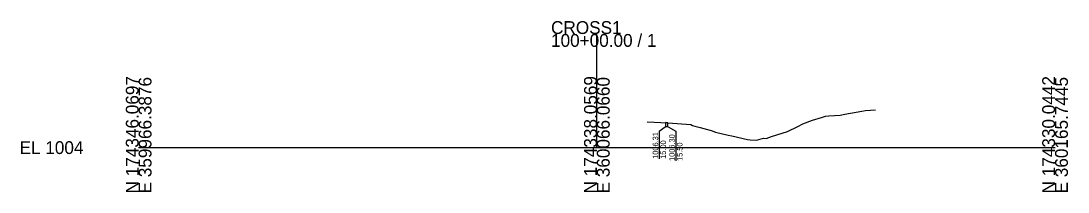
# Model space of a CAD drawing. Extents: x -26 to 1403, y -10 to 11027.
# Drawn here: x 1174.3 to 1402.8, y 3490.3 to 3527.6 of the extents above; entities that cross this region are included whole.
import ezdxf

# ---------------------------------------------------------------- set-up
doc = ezdxf.new("R2010")
doc.units = 0
for name, color, linetype in [('Default', 7, 'Continuous'), ('P_E_XS_Ground', 7, 'Continuous'), ('P_XS_EAR_CommonGrnd', 7, 'Continuous'), ('P_XS_Lane', 7, 'Continuous'), ('P_XS_Rock', 7, 'Continuous')]:
    doc.layers.add(name, color=color, linetype=linetype)

msp = doc.modelspace()

# ---------------------------------------------------------------- linework, layer by layer
at = {"layer": 'Default'}
for p, q in [((1300, 3500), (1300, 3524.78)), ((1200, 3500), (1300, 3500)), ((1300, 3500), (1400, 3500))]:
    msp.add_line(p, q, dxfattribs=at)
at = {"layer": 'P_E_XS_Ground'}
for p, q in [((1357.84, 3507.92), (1358.6, 3508.06)), ((1358.6, 3508.06), (1360.78, 3508.26)), ((1344.96, 3505.21), (1347.1, 3506.01)), ((1347.1, 3506.01), (1349.01, 3506.58)), ((1349.01, 3506.58), (1349.91, 3506.86)), ((1349.91, 3506.86), (1350.65, 3506.95)), ((1350.65, 3506.95), (1353.11, 3507.11)), ((1353.11, 3507.11), (1354.09, 3507.26)), ((1354.09, 3507.26), (1357.84, 3507.92)), ((1311, 3505.61), (1315.5, 3505.43)), ((1315.5, 3505.43), (1320.5, 3505.03)), ((1320.5, 3505.03), (1320.9, 3504.83)), ((1320.9, 3504.83), (1321.35, 3504.7)), ((1321.35, 3504.7), (1322.57, 3504.37)), ((1322.57, 3504.37), (1324.98, 3503.75)), ((1324.98, 3503.75), (1325.89, 3503.36)), ((1338.11, 3502.42), (1341.63, 3503.49)), ((1341.63, 3503.49), (1343.84, 3504.64)), ((1343.84, 3504.64), (1344.96, 3505.21)), ((1325.89, 3503.36), (1328.63, 3502.72)), ((1328.63, 3502.72), (1329.46, 3502.57)), ((1329.46, 3502.57), (1332.85, 3501.74)), ((1332.85, 3501.74), (1333.46, 3501.68)), ((1333.46, 3501.68), (1334.87, 3501.63)), ((1334.87, 3501.63), (1336.4, 3502.07)), ((1336.4, 3502.07), (1336.98, 3501.99)), ((1336.98, 3501.99), (1338.11, 3502.42))]:
    msp.add_line(p, q, dxfattribs=at)
at = {"layer": 'P_XS_EAR_CommonGrnd'}
msp.add_lwpolyline([(1315, 3504.62), (1315.5, 3504.6), (1315.5, 3505.43), (1315, 3505.45)], close=True, dxfattribs=at)
at = {"layer": 'P_XS_Lane'}
for p, q in [((1315, 3505.45), (1315, 3504.62)), ((1315, 3504.62), (1315.5, 3504.6)), ((1315.5, 3504.6), (1315.5, 3505.43))]:
    msp.add_line(p, q, dxfattribs=at)
at = {"layer": 'P_XS_Rock'}
for p, q in [((1313.63, 3503.61), (1314.9, 3504.55)), ((1313.63, 3503.61), (1313.63, 3497.56)), ((1315.59, 3504.54), (1317.24, 3503.55)), ((1317.24, 3503.55), (1317.24, 3497.1))]:
    msp.add_line(p, q, dxfattribs=at)

# ---------------------------------------------------------------- texts
at = {"layer": 'Default'}
for s, p in [('CROSS1', (1290, 3524.78)), ('100+00.00 / 1', (1290, 3521.98)), ('EL 1004', (1174, 3498.6))]:
    msp.add_text(s, height=2.8, dxfattribs=at).set_placement(p)
for s, p in [('N 174346.0697', (1200, 3490)), ('E 359966.3876', (1202.8, 3490)), ('N 174338.0569', (1300, 3490)), ('E 360066.0660', (1302.8, 3490)), ('N 174330.0442', (1400, 3490)), ('E 360165.7445', (1402.8, 3490))]:
    msp.add_text(s, height=2.8, rotation=90, dxfattribs=at).set_placement(p)
at = {"layer": 'P_XS_Rock'}
for s, p in [('1006.31', (1313.38, 3497.56)), ('15.00', (1315.08, 3497.56)), ('1006.30', (1316.99, 3497.1)), ('15.50', (1318.69, 3497.1))]:
    msp.add_text(s, height=1.2, rotation=90, dxfattribs=at).set_placement(p)

doc.saveas('drawing.dxf')
